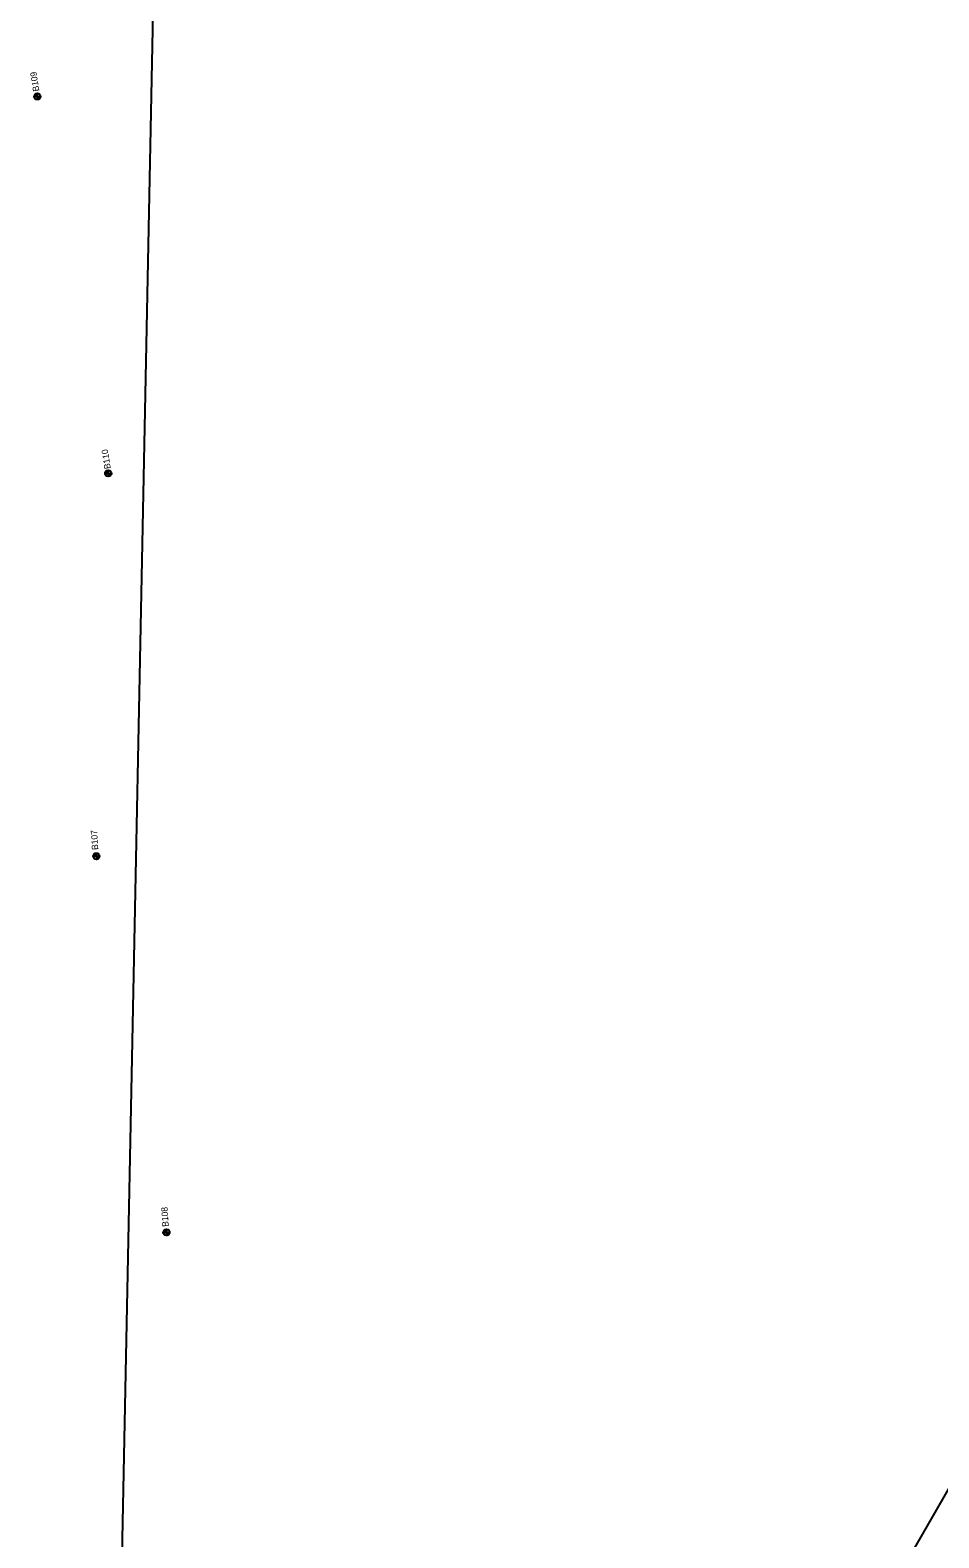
# Model space of a CAD drawing. Extents: x 345549 to 379569, y 127949 to 230467.
# Drawn here: x 355339 to 356769, y 186721 to 189095 of the extents above; entities that cross this region are included whole.
import ezdxf

# ---------------------------------------------------------------- set-up
doc = ezdxf.new("R2010")
doc.units = 0
for name, color, linetype in [('E_RDWY', 7, 'Continuous'), ('E_SOIL_BORE1 [KAPUR_CADDS_LEVELS]', 7, 'Continuous'), ('E_SOIL_BORE2 [KAPUR_CADDS_LEVELS]', 7, 'Continuous'), ('P_MARK', 7, 'Continuous')]:
    doc.layers.add(name, color=color, linetype=linetype)

msp = doc.modelspace()

# ---------------------------------------------------------------- linework, layer by layer
at = {"layer": 'E_RDWY'}
for p, q in [((355372.5, 181177.5), (356094.5, 217027.6)), ((358200.3, 189259.9), (355438.6, 184458.8))]:
    msp.add_line(p, q, dxfattribs=at)
at = {"layer": 'P_MARK'}
for p, q in [((355344.9, 188991.1), (355354.9, 188991.1)), ((355349.9, 188996.1), (355349.9, 188986.1)), ((355456.5, 188397.5), (355466.5, 188397.5)), ((355461.5, 188402.5), (355461.5, 188392.5)), ((355437.9, 187794.5), (355447.9, 187794.5)), ((355442.9, 187799.5), (355442.9, 187789.5)), ((355548.2, 187202.1), (355558.2, 187202.1)), ((355553.2, 187207.1), (355553.2, 187197.1))]:
    msp.add_line(p, q, dxfattribs=at)
for centre in [(355349.9, 188991.1), (355461.5, 188397.5), (355442.9, 187794.5), (355553.2, 187202.1)]:
    msp.add_circle(centre, 5, dxfattribs=at)
for centre, radius, start, end in [((355349.9, 188991.1), 4.5, 89.9869, 179.9869), ((355349.9, 188991.1), 4, 89.9869, 179.9869), ((355349.9, 188991.1), 3.5, 89.9869, 179.9869), ((355349.9, 188991.1), 3, 89.9869, 179.9869), ((355349.9, 188991.1), 2.5, 89.9869, 179.9869), ((355349.9, 188991.1), 2, 89.9869, 179.9869), ((355349.9, 188991.1), 1.5, 89.9869, 179.9869), ((355349.9, 188991.1), 1, 89.9869, 179.9869), ((355349.9, 188991.1), 0.5, 89.9869, 179.9869), ((355349.9, 188991.1), 4.5, 269.9869, 359.9869), ((355349.9, 188991.1), 4, 269.9869, 359.9869), ((355349.9, 188991.1), 3.5, 269.9869, 359.9869), ((355349.9, 188991.1), 3, 269.9869, 359.9869), ((355349.9, 188991.1), 2.5, 269.9869, 359.9869), ((355349.9, 188991.1), 2, 269.9869, 359.9869), ((355349.9, 188991.1), 1.5, 269.9869, 359.9869), ((355349.9, 188991.1), 1, 269.9869, 359.9869), ((355349.9, 188991.1), 0.5, 269.9869, 359.9869), ((355461.5, 188397.5), 4.5, 89.9869, 179.9869), ((355461.5, 188397.5), 4, 89.9869, 179.9869), ((355461.5, 188397.5), 3.5, 89.9869, 179.9869), ((355461.5, 188397.5), 3, 89.9869, 179.9869), ((355461.5, 188397.5), 2.5, 89.9869, 179.9869), ((355461.5, 188397.5), 2, 89.9869, 179.9869), ((355461.5, 188397.5), 1.5, 89.9869, 179.9869), ((355461.5, 188397.5), 1, 89.9869, 179.9869), ((355461.5, 188397.5), 0.5, 89.9869, 179.9869), ((355461.5, 188397.5), 4.5, 269.9869, 359.9869), ((355461.5, 188397.5), 4, 269.9869, 359.9869), ((355461.5, 188397.5), 3.5, 269.9869, 359.9869), ((355461.5, 188397.5), 3, 269.9869, 359.9869), ((355461.5, 188397.5), 2.5, 269.9869, 359.9869), ((355461.5, 188397.5), 2, 269.9869, 359.9869), ((355461.5, 188397.5), 1.5, 269.9869, 359.9869), ((355461.5, 188397.5), 1, 269.9869, 359.9869), ((355461.5, 188397.5), 0.5, 269.9869, 359.9869), ((355442.9, 187794.5), 4.5, 89.9869, 179.9869), ((355442.9, 187794.5), 4, 89.9869, 179.9869), ((355442.9, 187794.5), 3.5, 89.9869, 179.9869), ((355442.9, 187794.5), 3, 89.9869, 179.9869), ((355442.9, 187794.5), 2.5, 89.9869, 179.9869), ((355442.9, 187794.5), 2, 89.9869, 179.9869), ((355442.9, 187794.5), 1.5, 89.9869, 179.9869), ((355442.9, 187794.5), 1, 89.9869, 179.9869), ((355442.9, 187794.5), 0.5, 89.9869, 179.9869), ((355442.9, 187794.5), 4.5, 269.9869, 359.9869), ((355442.9, 187794.5), 4, 269.9869, 359.9869), ((355442.9, 187794.5), 3.5, 269.9869, 359.9869), ((355442.9, 187794.5), 3, 269.9869, 359.9869), ((355442.9, 187794.5), 2.5, 269.9869, 359.9869), ((355442.9, 187794.5), 2, 269.9869, 359.9869), ((355442.9, 187794.5), 1.5, 269.9869, 359.9869), ((355442.9, 187794.5), 1, 269.9869, 359.9869), ((355442.9, 187794.5), 0.5, 269.9869, 359.9869), ((355553.2, 187202.1), 4.5, 89.9869, 179.9869), ((355553.2, 187202.1), 4, 89.9869, 179.9869), ((355553.2, 187202.1), 3.5, 89.9869, 179.9869), ((355553.2, 187202.1), 3, 89.9869, 179.9869), ((355553.2, 187202.1), 2.5, 89.9869, 179.9869), ((355553.2, 187202.1), 2, 89.9869, 179.9869), ((355553.2, 187202.1), 1.5, 89.9869, 179.9869), ((355553.2, 187202.1), 1, 89.9869, 179.9869), ((355553.2, 187202.1), 0.5, 89.9869, 179.9869), ((355553.2, 187202.1), 4.5, 269.9869, 359.9869), ((355553.2, 187202.1), 4, 269.9869, 359.9869), ((355553.2, 187202.1), 3.5, 269.9869, 359.9869), ((355553.2, 187202.1), 3, 269.9869, 359.9869), ((355553.2, 187202.1), 2.5, 269.9869, 359.9869), ((355553.2, 187202.1), 2, 269.9869, 359.9869), ((355553.2, 187202.1), 1.5, 269.9869, 359.9869), ((355553.2, 187202.1), 1, 269.9869, 359.9869), ((355553.2, 187202.1), 0.5, 269.9869, 359.9869)]:
    msp.add_arc(centre, radius, start, end, dxfattribs=at)

# ---------------------------------------------------------------- texts
at = {"layer": 'E_SOIL_BORE1 [KAPUR_CADDS_LEVELS]'}
for s, p in [('B107', (355445.9, 187804.7)), ('B108', (355556.8, 187211.2))]:
    msp.add_text(s, height=10, rotation=93.5868, dxfattribs=at).set_placement(p)
at = {"layer": 'E_SOIL_BORE2 [KAPUR_CADDS_LEVELS]'}
for s, p in [('B109', (355353.2, 188999.7)), ('B110', (355465.6, 188405.1))]:
    msp.add_text(s, height=10, rotation=98.957, dxfattribs=at).set_placement(p)

doc.saveas('drawing.dxf')
